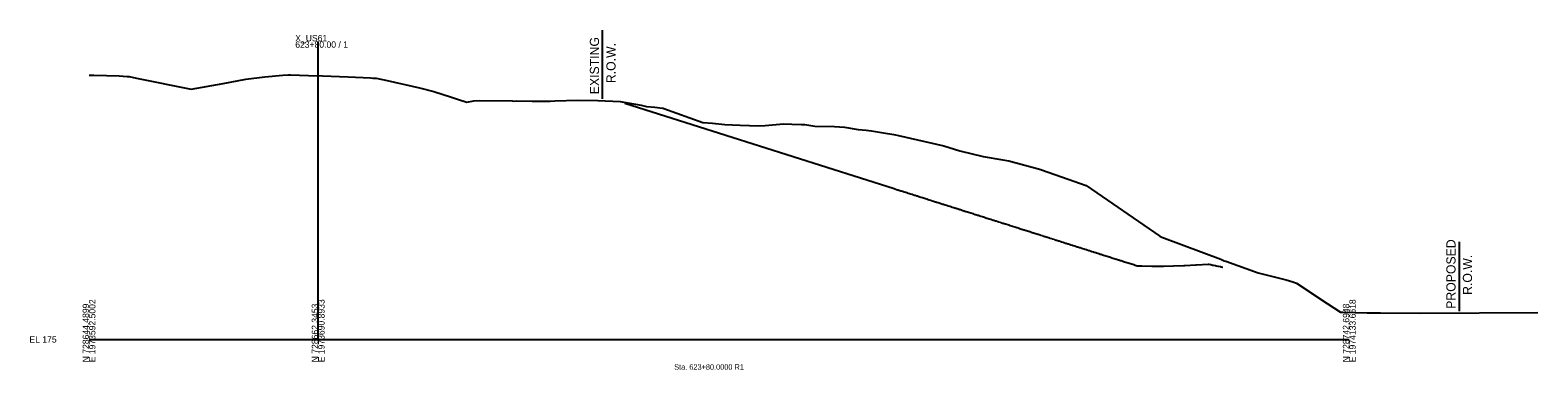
# Model space of a CAD drawing. Extents: x -26 to 1629, y -25 to 9635.
# Drawn here: x -26 to 632, y 9487 to 9635 of the extents above; entities that cross this region are included whole.
import ezdxf

# ---------------------------------------------------------------- set-up
doc = ezdxf.new("R2010")
doc.units = 0
for name, color, linetype in [('Draft_XS_Grid', 7, 'Continuous'), ('Draft_XS_Text', 7, 'Continuous'), ('DTM_X_GROUND', 7, 'Continuous'), ('XS_CELL', 7, 'Continuous'), ('XS_P_GROUND', 7, 'Continuous'), ('XS_P_ROW', 7, 'Continuous'), ('XS_X_ROW', 7, 'Continuous')]:
    doc.layers.add(name, color=color, linetype=linetype)

msp = doc.modelspace()

# ---------------------------------------------------------------- linework, layer by layer
at = {"layer": 'DTM_X_GROUND'}
msp.add_lwpolyline([(0, 9615.3), (2.05, 9615.26), (13.21, 9615.01), (16.68, 9614.72), (17.46, 9614.65), (20.68, 9613.99), (44.55, 9609.17), (58.49, 9611.68), (68.49, 9613.55), (76.69, 9614.53), (84.56, 9615.28), (87.08, 9615.39), (87.93, 9615.42), (95.81, 9615.17), (101.88, 9614.97), (113.13, 9614.48), (122.77, 9614.07), (123.87, 9613.99), (125.29, 9613.89), (130.11, 9612.99), (144.21, 9609.79), (150.55, 9608.18), (158.22, 9605.62), (159.55, 9605.2), (160.85, 9604.85), (164.87, 9603.53), (167.95, 9604), (170.6, 9604.21), (184.6, 9604.02), (185.18, 9603.95), (186.51, 9604), (193.4, 9603.91), (197.89, 9603.88), (201.21, 9603.98), (203.22, 9604.09), (213.33, 9604.33), (222.05, 9604.14), (231.74, 9603.76), (240.91, 9602.14), (243.35, 9601.63), (246.86, 9601.33), (250.21, 9600.88), (250.62, 9600.82), (250.92, 9600.77), (267.88, 9594.6), (272.15, 9594.37), (277.45, 9593.69), (284.15, 9593.42), (292.32, 9593.09), (295.14, 9593.26), (301.53, 9593.94), (303, 9594.09), (306.79, 9593.86), (310.92, 9593.79), (312.35, 9593.71), (316.79, 9592.97), (325.36, 9592.82), (329.67, 9592.65), (335.74, 9591.59), (339.17, 9591.21), (341.45, 9590.92), (346.77, 9590.05), (351.25, 9589.37), (351.98, 9589.21), (353.29, 9588.93), (373.04, 9584.42), (380.01, 9582.2), (390.16, 9579.83), (398.81, 9578.36), (401.49, 9577.92), (415.39, 9574.13), (415.74, 9574.03), (427.26, 9569.88), (435.15, 9567.11), (467.29, 9545), (467.34, 9544.97), (467.41, 9544.94), (469.29, 9544.22), (493.96, 9534.97), (495.41, 9534.3), (496.13, 9534.12), (510.19, 9529.03), (522.43, 9526.04), (525.43, 9525.06), (527, 9524.52), (540.39, 9515.61), (546.16, 9511.91), (547.17, 9511.87), (557.82, 9511.52), (563.66, 9511.52), (581.3, 9511.45), (632.3, 9511.76)], dxfattribs=at)
at = {"layer": 'XS_CELL'}
for p, q in [((100, 9500), (100, 9630)), ((0, 9500), (100, 9500)), ((100, 9500), (550, 9500))]:
    msp.add_line(p, q, dxfattribs=at)
at = {"layer": 'XS_P_GROUND'}
msp.add_lwpolyline([(233.91, 9603.05), (351.44, 9565.76), (351.69, 9565.68), (352.45, 9565.44), (352.85, 9565.31), (353.15, 9565.22), (353.46, 9565.12), (354.32, 9564.85), (354.47, 9564.8), (355.01, 9564.63), (355.48, 9564.48), (355.68, 9564.42), (356.49, 9564.16), (356.95, 9564.01), (357.5, 9563.84), (358.13, 9563.64), (358.51, 9563.52), (359.24, 9563.29), (359.52, 9563.2), (360.27, 9562.96), (360.53, 9562.88), (361.24, 9562.65), (361.54, 9562.56), (362.14, 9562.37), (362.55, 9562.24), (363, 9562.09), (363.56, 9561.92), (363.74, 9561.86), (364.57, 9561.59), (365.02, 9561.45), (365.58, 9561.27), (366.25, 9561.06), (366.59, 9560.95), (367.45, 9560.68), (367.6, 9560.63), (368.59, 9560.32), (368.61, 9560.31), (369.42, 9560.06), (369.62, 9559.99), (369.83, 9559.93), (370.57, 9559.69), (370.62, 9559.68), (370.63, 9559.67), (371.39, 9559.43), (371.64, 9559.35), (371.76, 9559.31), (372.65, 9559.03), (372.85, 9558.97), (372.96, 9558.93), (373.21, 9558.86), (373.66, 9558.71), (374.23, 9558.53), (374.67, 9558.39), (374.89, 9558.32), (375.68, 9558.07), (376.16, 9557.92), (376.37, 9557.85), (376.47, 9557.82), (376.69, 9557.75), (377.36, 9557.54), (377.7, 9557.43), (377.93, 9557.36), (378.22, 9557.27), (378.49, 9557.18), (378.71, 9557.11), (378.76, 9557.09), (378.82, 9557.07), (379.3, 9556.92), (379.51, 9556.85), (379.57, 9556.84), (379.72, 9556.79), (380.08, 9556.67), (380.21, 9556.63), (380.34, 9556.59), (380.73, 9556.47), (380.84, 9556.43), (380.93, 9556.4), (381.32, 9556.28), (381.75, 9556.15), (382.03, 9556.06), (382.11, 9556.03), (382.26, 9555.98), (382.67, 9555.85), (382.71, 9555.84), (382.76, 9555.83), (383.37, 9555.63), (383.77, 9555.51), (383.79, 9555.5), (384.78, 9555.18), (384.86, 9555.16), (385.79, 9554.86), (385.96, 9554.81), (386.8, 9554.54), (387.05, 9554.46), (387.81, 9554.22), (388.14, 9554.12), (388.82, 9553.9), (389.22, 9553.77), (389.83, 9553.58), (390.3, 9553.43), (390.84, 9553.26), (391.37, 9553.09), (391.85, 9552.94), (392.45, 9552.75), (392.86, 9552.62), (393.51, 9552.41), (393.87, 9552.3), (394.58, 9552.07), (394.88, 9551.98), (395.64, 9551.74), (395.89, 9551.66), (396.6, 9551.43), (396.77, 9551.38), (396.87, 9551.35), (396.9, 9551.34), (397.76, 9551.07), (397.91, 9551.02), (398.72, 9550.76), (398.81, 9550.73), (398.91, 9550.7), (398.92, 9550.7), (399.87, 9550.4), (399.93, 9550.38), (400.92, 9550.06), (400.94, 9550.06), (401.39, 9549.91), (401.95, 9549.74), (401.95, 9549.73), (402.96, 9549.42), (402.98, 9549.41), (403.97, 9549.1), (404, 9549.08), (404.98, 9548.77), (405.03, 9548.76), (405.99, 9548.45), (406.05, 9548.43), (407, 9548.13), (407.07, 9548.11), (408.01, 9547.81), (408.1, 9547.78), (409.02, 9547.49), (409.12, 9547.46), (410.03, 9547.17), (410.14, 9547.14), (411.04, 9546.85), (411.16, 9546.81), (412.05, 9546.53), (412.19, 9546.49), (413.06, 9546.21), (413.21, 9546.16), (414.07, 9545.89), (414.23, 9545.84), (415.08, 9545.57), (415.25, 9545.51), (416.09, 9545.25), (416.27, 9545.19), (417.1, 9544.93), (417.29, 9544.87), (418.11, 9544.61), (418.31, 9544.54), (419.12, 9544.29), (419.33, 9544.22), (420.13, 9543.97), (420.35, 9543.9), (421.14, 9543.65), (421.37, 9543.57), (422.15, 9543.33), (422.36, 9543.26), (423.03, 9543.05), (423.06, 9543.04), (423.16, 9543.01), (423.41, 9542.92), (424.17, 9542.69), (424.43, 9542.6), (425.18, 9542.36), (425.45, 9542.28), (426.19, 9542.04), (426.47, 9541.95), (427.2, 9541.72), (427.49, 9541.63), (428.21, 9541.4), (428.51, 9541.31), (429.22, 9541.08), (429.53, 9540.99), (430.23, 9540.76), (430.55, 9540.66), (431.24, 9540.44), (431.56, 9540.34), (432.25, 9540.12), (432.58, 9540.02), (433.26, 9539.8), (433.6, 9539.69), (434.27, 9539.48), (434.62, 9539.37), (435.28, 9539.16), (435.63, 9539.05), (436.29, 9538.84), (436.65, 9538.72), (437.3, 9538.52), (437.67, 9538.4), (438.31, 9538.2), (438.69, 9538.08), (439.32, 9537.88), (439.7, 9537.76), (440.33, 9537.56), (440.72, 9537.43), (441.34, 9537.24), (441.74, 9537.11), (442.35, 9536.92), (442.75, 9536.79), (443.36, 9536.6), (443.77, 9536.47), (444.37, 9536.28), (444.79, 9536.14), (445.38, 9535.96), (445.8, 9535.82), (446.39, 9535.63), (446.82, 9535.5), (447.4, 9535.31), (447.84, 9535.18), (448.41, 9534.99), (448.79, 9534.87), (449.29, 9534.72), (449.34, 9534.7), (449.42, 9534.67), (449.76, 9534.57), (450.18, 9534.43), (450.29, 9534.4), (450.43, 9534.35), (450.89, 9534.21), (451.44, 9534.03), (451.9, 9533.89), (452.45, 9533.71), (452.92, 9533.56), (453.46, 9533.39), (453.93, 9533.24), (454.47, 9533.07), (454.95, 9532.92), (455.48, 9532.75), (455.96, 9532.6), (456.49, 9532.43), (456.98, 9532.27), (457.5, 9532.11), (457.66, 9532.09), (459.18, 9532.04), (459.53, 9532.04), (463.89, 9531.99), (464.27, 9531.99), (468.59, 9532), (468.99, 9532.01), (473.33, 9532.09), (477.85, 9532.23), (478.2, 9532.24), (482.99, 9532.46), (483.29, 9532.48), (488.46, 9532.79), (488.67, 9532.8), (489.39, 9532.65), (489.65, 9532.6), (490.46, 9532.43), (490.75, 9532.38), (491.56, 9532.21), (491.84, 9532.15), (492.67, 9531.98), (492.93, 9531.93), (493.77, 9531.75), (494.02, 9531.7), (494.71, 9531.56), (494.89, 9531.52)], dxfattribs=at)
at = {"layer": 'XS_P_ROW'}
msp.add_line((598, 9542.59), (598, 9512.27), dxfattribs=at)
at = {"layer": 'XS_X_ROW'}
msp.add_line((224, 9634.9), (224, 9605), dxfattribs=at)

# ---------------------------------------------------------------- texts
at = {"layer": 'Draft_XS_Grid'}
msp.add_text('-', height=0.0001, dxfattribs=at).set_placement((0, 9500))
at = {"layer": 'Draft_XS_Text'}
msp.add_text('Sta. 623+80.0000 R1', height=2.4, dxfattribs=at).set_placement((255.38, 9486.75))
at = {"layer": 'XS_CELL'}
for s, p in [('X_US61', (90, 9630)), ('623+80.00 / 1', (90, 9627.2)), ('EL 175', (-26, 9498.6))]:
    msp.add_text(s, height=2.8, dxfattribs=at).set_placement(p)
for s, p in [('N 728644.4899', (0, 9490)), ('E 1973592.5002', (2.8, 9490)), ('N 728662.3453', (100, 9490)), ('E 1973690.8933', (102.8, 9490)), ('N 728742.6948', (550, 9490)), ('E 1974133.6618', (552.8, 9490))]:
    msp.add_text(s, height=2.8, rotation=90, dxfattribs=at).set_placement(p)
at = {"layer": 'XS_P_ROW'}
for s, p in [('PROPOSED', (596.37, 9513.33)), ('R.O.W.', (603.57, 9519.4))]:
    msp.add_text(s, height=4, rotation=90, dxfattribs=at).set_placement(p)
at = {"layer": 'XS_X_ROW'}
for s, p in [('EXISTING', (222.58, 9606.94)), ('R.O.W.', (229.78, 9611.78))]:
    msp.add_text(s, height=4, rotation=90, dxfattribs=at).set_placement(p)

doc.saveas('drawing.dxf')
